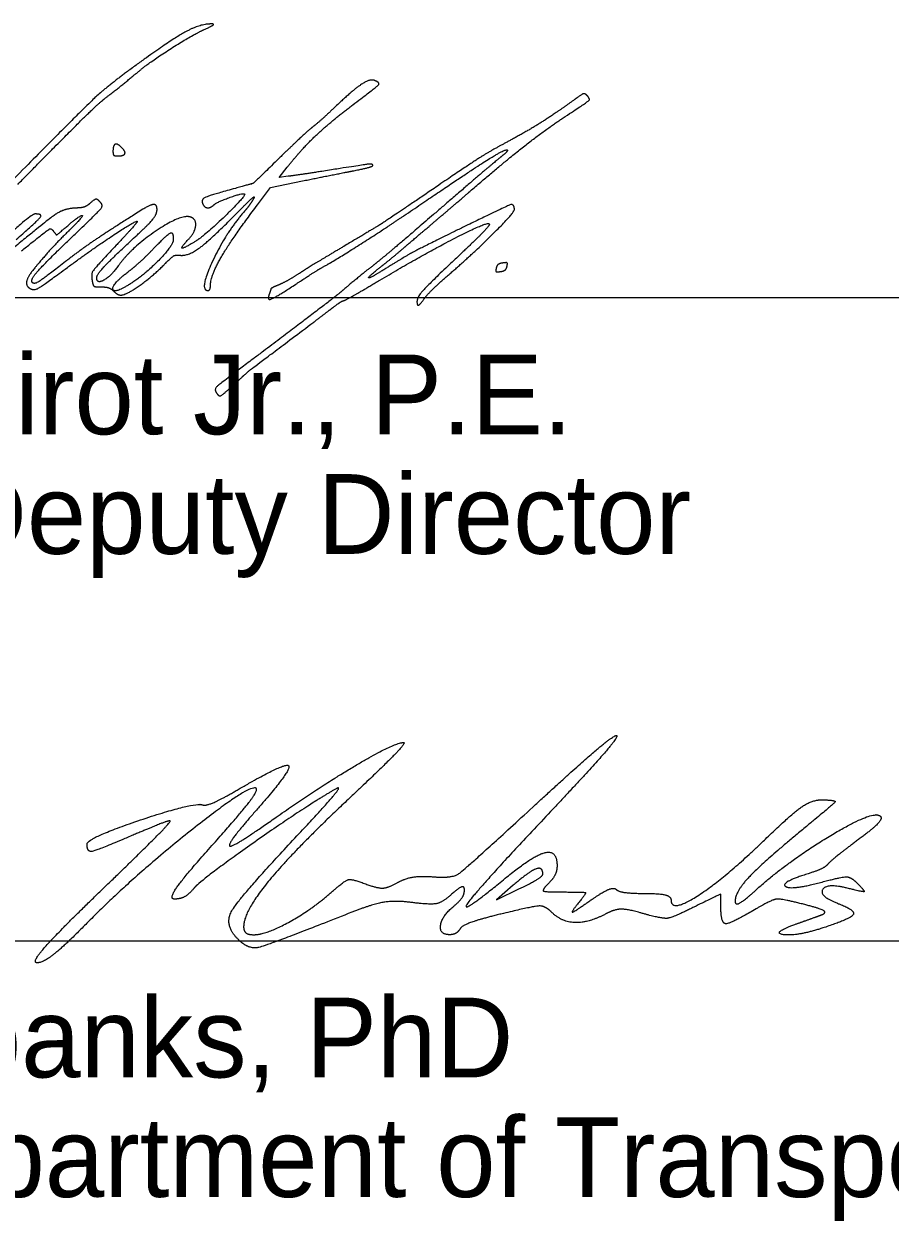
# Model space of a CAD drawing. Extents: x 0 to 34, y 0 to 22.
# Drawn here: x 25.594 to 27.114, y 7.177 to 9.279 of the extents above; entities that cross this region are included whole.
import ezdxf

# ---------------------------------------------------------------- set-up
doc = ezdxf.new("R2010")
doc.units = 0
doc.layers.add('SH_Data', color=7, linetype='Continuous')
doc.layers.add('SH_Text', color=7, linetype='Continuous')

msp = doc.modelspace()

# ---------------------------------------------------------------- linework, layer by layer
at = {"layer": 'SH_Data'}
for p, q in [((24.5279, 8.7985), (28.0279, 8.7985)), ((24.5279, 7.6691), (28.0279, 7.6691))]:
    msp.add_line(p, q, dxfattribs=at)
at = {"layer": 'SH_Text'}
for p, q in [((26.5045, 7.7863), (26.5045, 7.7863)), ((25.7273, 7.7552), (25.7273, 7.7552))]:
    msp.add_line(p, q, dxfattribs=at)
for points in [[(26.0579, 9.0115), (26.0419, 9.0095), (26.0559, 9.0273)], [(26.0039, 8.9616), (26.0269, 8.992), (26.083, 9.0034)], [(26.4527, 7.7666), (26.4232, 7.741), (26.4638, 7.7606)]]:
    msp.add_lwpolyline(points, dxfattribs=at)
for points in [[(25.9248, 9.279), (25.9035, 9.2798), (25.8469, 9.2481), (25.7754, 9.1954)], [(25.9102, 9.2692), (25.9219, 9.2745), (25.9284, 9.2789), (25.9248, 9.279)], [(25.7973, 9.1975), (25.8146, 9.2121), (25.8898, 9.2599), (25.9102, 9.2692)], [(25.7754, 9.1954), (25.7371, 9.1671), (25.6966, 9.1288), (25.567, 8.9978)], [(25.7351, 9.1475), (25.7574, 9.1649), (25.7844, 9.1866), (25.7973, 9.1975)], [(26.2088, 9.1799), (26.2008, 9.1829), (26.1702, 9.1621), (26.139, 9.1324)], [(26.1713, 9.137), (26.2132, 9.1687), (26.2194, 9.1758), (26.2088, 9.1799)], [(25.583, 8.9972), (25.6555, 9.0713), (25.724, 9.1389), (25.7351, 9.1475)], [(26.5615, 9.1472), (26.532, 9.1255), (26.4808, 9.0927), (26.4529, 9.0777)], [(26.5402, 9.1141), (26.5831, 9.1423), (26.5882, 9.1473), (26.5813, 9.1541)], [(26.5813, 9.1541), (26.5781, 9.1573), (26.5726, 9.1554), (26.5615, 9.1472)], [(26.0559, 9.0273), (26.0807, 9.0588), (26.1299, 9.1056), (26.1713, 9.137)], [(26.139, 9.1324), (26.1256, 9.1195), (26.1082, 9.104), (26.1004, 9.0978)], [(26.3772, 8.9855), (26.4315, 9.0325), (26.5078, 9.0927), (26.5402, 9.1141)], [(26.1004, 9.0978), (26.0925, 9.0916), (26.066, 9.0668), (26.0413, 9.0428)], [(25.7653, 9.0623), (25.7579, 9.0697), (25.7502, 9.066), (25.7502, 9.0551)], [(25.7581, 9.0472), (25.7691, 9.0472), (25.7728, 9.0549), (25.7653, 9.0623)], [(26.4529, 9.0777), (26.4131, 9.0563), (26.383, 9.0375), (26.3223, 8.9962)], [(25.7502, 9.0551), (25.7502, 9.05), (25.753, 9.0472), (25.7581, 9.0472)], [(26.0413, 9.0428), (25.9974, 8.9999), (25.9959, 8.9989), (25.965, 8.9903)], [(26.2612, 8.9425), (26.3674, 9.015), (26.4424, 9.0624), (26.4424, 9.0571)], [(26.4312, 9.0457), (26.4251, 9.0409), (26.3861, 9.0077), (26.3446, 8.9719)], [(26.4424, 9.0571), (26.4424, 9.0557), (26.4374, 9.0505), (26.4312, 9.0457)], [(26.1166, 9.0202), (26.0931, 9.0165), (26.0667, 9.0126), (26.0579, 9.0115)], [(26.083, 9.0034), (26.1138, 9.0097), (26.1542, 9.0177), (26.1726, 9.0213)], [(26.2062, 9.0307), (26.2062, 9.0337), (26.1895, 9.0317), (26.1166, 9.0202)], [(26.1726, 9.0213), (26.1911, 9.0249), (26.2062, 9.0292), (26.2062, 9.0307)], [(25.9811, 8.9805), (25.984, 8.9777), (25.9133, 8.909), (25.8969, 8.8986)], [(25.965, 8.9903), (25.9191, 8.9777), (25.9047, 8.971), (25.9075, 8.9637)], [(25.9276, 8.9616), (25.9324, 8.9663), (25.9789, 8.9828), (25.9811, 8.9805)], [(26.3223, 8.9962), (26.2337, 8.936), (26.2145, 8.9237), (26.1553, 8.8885)], [(26.3243, 8.9402), (26.3478, 8.9602), (26.3716, 8.9806), (26.3772, 8.9855)], [(25.6859, 8.9558), (25.6653, 8.9553), (25.6339, 8.9343), (25.5531, 8.867)], [(25.6818, 8.9082), (25.7239, 8.9487), (25.7332, 8.9596), (25.7295, 8.9642)], [(25.7087, 8.963), (25.7045, 8.9592), (25.6943, 8.9559), (25.6859, 8.9558)], [(25.7295, 8.9642), (25.7233, 8.9716), (25.7179, 8.9713), (25.7087, 8.963)], [(25.8275, 8.9527), (25.8276, 8.9619), (25.8169, 8.9623), (25.8027, 8.9535)], [(25.9075, 8.9637), (25.9102, 8.9568), (25.9216, 8.9556), (25.9276, 8.9616)], [(25.9212, 8.8193), (25.9212, 8.8369), (25.9595, 8.9028), (26.0039, 8.9616)], [(25.9678, 8.947), (25.9878, 8.9674), (26.0008, 8.9786), (25.9967, 8.9719)], [(25.9967, 8.9719), (25.9927, 8.9651), (25.9861, 8.956), (25.9822, 8.9515)], [(26.3446, 8.9719), (26.2759, 8.9125), (26.2222, 8.867), (26.2062, 8.8545)], [(26.4546, 8.9531), (26.4546, 8.9639), (26.4407, 8.9591), (26.3661, 8.9227)], [(25.6135, 8.9454), (25.6063, 8.9454), (25.4979, 8.844), (25.4978, 8.8373)], [(25.5805, 8.9005), (25.6185, 8.9337), (25.6271, 8.9454), (25.6135, 8.9454)], [(25.665, 8.9199), (25.6913, 8.9427), (25.7002, 8.9428), (25.6769, 8.92)], [(25.8027, 8.9535), (25.7468, 8.9186), (25.6936, 8.8827), (25.667, 8.8619)], [(25.8869, 8.9397), (25.8709, 8.9459), (25.7822, 8.8863), (25.7595, 8.8542)], [(25.789, 8.905), (25.8124, 8.9265), (25.8274, 8.9452), (25.8275, 8.9527)], [(25.8678, 8.8728), (25.8826, 8.8713), (25.9225, 8.9009), (25.9678, 8.947)], [(25.8818, 8.8998), (25.8939, 8.9125), (25.8969, 8.9359), (25.8869, 8.9397)], [(25.9822, 8.9515), (25.9489, 8.9136), (25.901, 8.811), (25.9166, 8.811)], [(26.1146, 8.8499), (26.1373, 8.8625), (26.2253, 8.9181), (26.2612, 8.9425)], [(26.2595, 8.8849), (26.2716, 8.8953), (26.3008, 8.9202), (26.3243, 8.9402)], [(26.3385, 8.8379), (26.3792, 8.8728), (26.4546, 8.9477), (26.4546, 8.9531)], [(25.5896, 8.8805), (25.6356, 8.9173), (25.6415, 8.9209), (25.646, 8.9147)], [(25.6769, 8.92), (25.6555, 8.899), (25.6324, 8.874), (25.6129, 8.8506)], [(25.646, 8.9147), (25.6507, 8.9083), (25.6523, 8.9088), (25.665, 8.9199)], [(25.6702, 8.8514), (25.714, 8.8837), (25.7909, 8.9346), (25.7929, 8.9326)], [(25.7929, 8.9326), (25.7936, 8.9318), (25.777, 8.9128), (25.7559, 8.8904)], [(26.2184, 8.8291), (26.3001, 8.8777), (26.4157, 8.9361), (26.4102, 8.9258)], [(26.3661, 8.9227), (26.2919, 8.8864), (26.2627, 8.8707), (26.2211, 8.8447)], [(26.4102, 8.9258), (26.4079, 8.9215), (26.3821, 8.8955), (26.3529, 8.868)], [(25.609, 8.8247), (25.6045, 8.8292), (25.6294, 8.8578), (25.6818, 8.9082)], [(25.7217, 8.8333), (25.7217, 8.8389), (25.7502, 8.8692), (25.789, 8.905)], [(25.8561, 8.9004), (25.8561, 8.8909), (25.8096, 8.8419), (25.7853, 8.8257)], [(25.821, 8.8841), (25.846, 8.9098), (25.8561, 8.9145), (25.8561, 8.9004)], [(25.8969, 8.8986), (25.8754, 8.8851), (25.8682, 8.8856), (25.8818, 8.8998)], [(25.7559, 8.8904), (25.7183, 8.8505), (25.7114, 8.8396), (25.7143, 8.8246)], [(25.7777, 8.8446), (25.7883, 8.8527), (25.8078, 8.8705), (25.821, 8.8841)], [(25.8393, 8.8557), (25.8528, 8.8695), (25.8597, 8.8737), (25.8678, 8.8728)], [(26.1553, 8.8885), (26.124, 8.8699), (26.0887, 8.8484), (26.077, 8.8408)], [(26.2197, 8.8522), (26.2295, 8.8598), (26.2474, 8.8745), (26.2595, 8.8849)], [(25.6129, 8.8506), (25.6011, 8.8364), (25.5968, 8.8194), (25.6039, 8.815)], [(25.6039, 8.815), (25.6111, 8.8105), (25.6255, 8.8184), (25.6702, 8.8514)], [(25.667, 8.8619), (25.6291, 8.8323), (25.6122, 8.8215), (25.609, 8.8247)], [(25.7595, 8.8542), (25.7466, 8.8359), (25.7217, 8.8222), (25.7217, 8.8333)], [(25.764, 8.8029), (25.773, 8.8029), (25.8198, 8.8357), (25.8393, 8.8557)], [(26.2062, 8.8545), (26.1938, 8.8449), (26.1553, 8.8131), (26.1533, 8.8109)], [(26.2211, 8.8447), (26.1993, 8.831), (26.1984, 8.8356), (26.2197, 8.8522)], [(26.3529, 8.868), (26.3016, 8.8197), (26.2813, 8.7955), (26.2844, 8.7863)], [(26.4227, 8.8504), (26.4216, 8.8446), (26.4234, 8.8433), (26.4308, 8.8443)], [(26.4336, 8.8592), (26.4283, 8.8585), (26.4235, 8.8545), (26.4227, 8.8504)], [(26.4308, 8.8443), (26.436, 8.845), (26.4409, 8.849), (26.4417, 8.8531)], [(26.4417, 8.8531), (26.4428, 8.8589), (26.4409, 8.8603), (26.4336, 8.8592)], [(25.7853, 8.8257), (25.7535, 8.8045), (25.7469, 8.8209), (25.7777, 8.8446)], [(26.077, 8.8408), (26.0653, 8.8332), (26.0492, 8.8243), (26.0414, 8.821)], [(26.0711, 8.8221), (26.0905, 8.8349), (26.1101, 8.8475), (26.1146, 8.8499)], [(26.2959, 8.7958), (26.3014, 8.8035), (26.3206, 8.8224), (26.3385, 8.8379)], [(25.7143, 8.8246), (25.7154, 8.8191), (25.7195, 8.8172), (25.7299, 8.8172)], [(25.7299, 8.8172), (25.738, 8.8173), (25.747, 8.8143), (25.7511, 8.8101)], [(25.7511, 8.8101), (25.7551, 8.8061), (25.7609, 8.8029), (25.764, 8.8029)], [(25.9166, 8.811), (25.9191, 8.811), (25.9212, 8.8148), (25.9212, 8.8193)], [(26.1533, 8.8109), (26.151, 8.8084), (26.0688, 8.7455), (25.9986, 8.6927)], [(26.0246, 8.8053), (26.0199, 8.793), (26.0353, 8.7986), (26.0711, 8.8221)], [(26.0271, 8.8134), (26.0271, 8.8124), (26.026, 8.8088), (26.0246, 8.8053)], [(26.0414, 8.821), (26.0335, 8.8177), (26.0271, 8.8143), (26.0271, 8.8134)], [(26.1552, 8.7932), (26.1575, 8.7936), (26.186, 8.8097), (26.2184, 8.8291)], [(26.1369, 8.7816), (26.1447, 8.7876), (26.153, 8.7928), (26.1552, 8.7932)], [(26.2844, 8.7863), (26.2852, 8.7838), (26.2904, 8.7881), (26.2959, 8.7958)], [(26.1024, 8.7554), (26.1136, 8.7638), (26.1291, 8.7756), (26.1369, 8.7816)], [(25.9616, 8.6451), (25.9862, 8.6678), (25.9937, 8.6737), (26.1024, 8.7554)], [(25.9986, 8.6927), (25.9381, 8.6471), (25.9277, 8.6378), (25.9311, 8.6323)], [(25.9311, 8.6323), (25.9359, 8.6246), (25.9421, 8.6272), (25.9616, 8.6451)], [(26.0326, 7.8833), (26.1131, 7.9399), (26.2445, 8.0172), (26.2602, 8.0172)], [(26.2602, 8.0172), (26.265, 8.0172), (26.2237, 7.9746), (26.1684, 7.9225)], [(26.4869, 7.9037), (26.5619, 7.9728), (26.6279, 8.0295), (26.6336, 8.0295)], [(26.6336, 8.0295), (26.6394, 8.0296), (26.5873, 7.9695), (26.518, 7.8959)], [(25.9736, 7.9368), (26.0524, 7.983), (26.0646, 7.9698), (26.0054, 7.9025)], [(26.0017, 7.9366), (25.9921, 7.9462), (25.7824, 7.7793), (25.7045, 7.7)], [(26.142, 7.9361), (26.0929, 7.9084), (25.9046, 7.7761), (25.8914, 7.7602)], [(25.908, 7.9076), (25.9136, 7.9058), (25.9431, 7.9189), (25.9736, 7.9368)], [(25.9239, 7.8362), (25.9702, 7.888), (26.0052, 7.9331), (26.0017, 7.9366)], [(26.0768, 7.8572), (26.123, 7.9065), (26.1523, 7.942), (26.142, 7.9361)], [(25.7047, 7.8391), (25.7049, 7.8496), (25.8923, 7.9128), (25.908, 7.9076)], [(26.1684, 7.9225), (26.0687, 7.8288), (25.9795, 7.7206), (25.9795, 7.6936)], [(26.8951, 7.8475), (26.9403, 7.8913), (26.9774, 7.917), (26.9951, 7.9166)], [(26.9951, 7.9166), (27.0194, 7.9161), (27.0156, 7.9098), (26.967, 7.8698)], [(26.0054, 7.9025), (25.9774, 7.8706), (25.9545, 7.841), (25.9545, 7.8365)], [(25.9545, 7.8365), (25.9545, 7.8321), (25.9896, 7.8531), (26.0326, 7.8833)], [(26.3119, 7.7814), (26.3453, 7.7786), (26.3688, 7.795), (26.4869, 7.9037)], [(26.518, 7.8959), (26.3885, 7.7583), (26.3564, 7.711), (26.4386, 7.7788)], [(26.8763, 7.7563), (26.93, 7.8051), (27.0769, 7.8951), (27.0938, 7.8895)], [(27.0938, 7.8895), (27.1022, 7.8867), (27.087, 7.868), (27.0599, 7.8478)], [(25.7273, 7.7552), (25.7983, 7.8237), (25.8537, 7.8797), (25.8502, 7.8797)], [(25.8502, 7.8797), (25.8468, 7.8797), (25.8178, 7.8684), (25.7857, 7.8547)], [(26.967, 7.8698), (26.8929, 7.8088), (26.842, 7.7553), (26.842, 7.7385)], [(25.7857, 7.8547), (25.7231, 7.8279), (25.7044, 7.8242), (25.7047, 7.8391)], [(25.9697, 7.6716), (25.9445, 7.6968), (25.9734, 7.7469), (26.0768, 7.8572)], [(26.7295, 7.7407), (26.7295, 7.7179), (26.8248, 7.7793), (26.8951, 7.8475)], [(27.0599, 7.8478), (27.0328, 7.8276), (27.0079, 7.8076), (27.0045, 7.8033)], [(25.8581, 7.7422), (25.8478, 7.7422), (25.8767, 7.7835), (25.9239, 7.8362)], [(26.4386, 7.7788), (26.487, 7.8187), (26.5295, 7.829), (26.5295, 7.8009)], [(26.5295, 7.8009), (26.5295, 7.792), (26.5227, 7.7779), (26.5145, 7.7697)], [(27.0045, 7.8033), (27.001, 7.7991), (26.9856, 7.7916), (26.9701, 7.7868)], [(26.2489, 7.7709), (26.2623, 7.7785), (26.2906, 7.7832), (26.3119, 7.7814)], [(26.5045, 7.7863), (26.5045, 7.7997), (26.4804, 7.7906), (26.4527, 7.7666)], [(26.4638, 7.7606), (26.4862, 7.7715), (26.5045, 7.783), (26.5045, 7.7863)], [(26.9701, 7.7868), (26.9206, 7.7713), (26.9401, 7.7577), (26.9919, 7.7715)], [(26.9919, 7.7715), (27.0302, 7.7817), (27.0455, 7.7811), (27.0575, 7.7689)], [(25.8914, 7.7602), (25.8831, 7.7503), (25.8682, 7.7422), (25.8581, 7.7422)], [(25.9975, 7.6797), (26.0192, 7.6797), (26.1006, 7.7249), (26.137, 7.7572)], [(26.137, 7.7572), (26.1573, 7.7752), (26.1701, 7.7779), (26.1939, 7.7688)], [(26.1939, 7.7688), (26.2141, 7.7612), (26.2329, 7.7619), (26.2489, 7.7709)], [(26.367, 7.7582), (26.367, 7.7653), (26.3568, 7.7619), (26.3444, 7.7506)], [(26.3482, 7.7297), (26.3585, 7.7382), (26.367, 7.7511), (26.367, 7.7582)], [(26.5145, 7.7697), (26.5028, 7.758), (26.5087, 7.7547), (26.541, 7.7547)], [(26.5871, 7.7392), (26.6085, 7.7542), (26.6293, 7.7632), (26.6332, 7.7593)], [(26.6332, 7.7593), (26.6371, 7.7554), (26.6604, 7.7522), (26.6849, 7.7522)], [(27.0388, 7.7614), (27.0021, 7.7705), (26.9889, 7.7474), (27.0232, 7.7342)], [(27.0575, 7.7689), (27.0702, 7.756), (27.0666, 7.7545), (27.0388, 7.7614)], [(25.617, 7.6304), (25.6067, 7.6306), (25.6563, 7.6868), (25.7273, 7.7552)], [(26.2749, 7.7362), (26.2457, 7.74), (26.2058, 7.7335), (26.1693, 7.7191)], [(26.3444, 7.7506), (26.3287, 7.7365), (26.3075, 7.732), (26.2749, 7.7362)], [(26.541, 7.7547), (26.5785, 7.7547), (26.5809, 7.7526), (26.5654, 7.7333)], [(26.5654, 7.7333), (26.5533, 7.7183), (26.5598, 7.7201), (26.5871, 7.7392)], [(26.6849, 7.7522), (26.7094, 7.7522), (26.7295, 7.747), (26.7295, 7.7407)], [(26.817, 7.7281), (26.817, 7.751), (26.8159, 7.751), (26.7698, 7.7282)], [(26.842, 7.7385), (26.842, 7.7311), (26.8574, 7.7391), (26.8763, 7.7563)], [(26.9621, 7.7331), (26.9233, 7.743), (26.9065, 7.7414), (26.8789, 7.7251)], [(26.1693, 7.7191), (26.0233, 7.6614), (25.9882, 7.6531), (25.9697, 7.6716)], [(26.3412, 7.6797), (26.3229, 7.6797), (26.3274, 7.7124), (26.3482, 7.7297)], [(26.4355, 7.7171), (26.3972, 7.7079), (26.3629, 7.6958), (26.3594, 7.6901)], [(26.5199, 7.7193), (26.5088, 7.7304), (26.4887, 7.7299), (26.4355, 7.7171)], [(26.6162, 7.7168), (26.5854, 7.7003), (26.5376, 7.7016), (26.5199, 7.7193)], [(26.6807, 7.7168), (26.6538, 7.7246), (26.6307, 7.7245), (26.6162, 7.7168)], [(26.7698, 7.7282), (26.7324, 7.7097), (26.7138, 7.7073), (26.6807, 7.7168)], [(26.8789, 7.7251), (26.8339, 7.6985), (26.817, 7.6993), (26.817, 7.7281)], [(26.992, 7.7139), (27.0034, 7.7181), (26.9917, 7.7256), (26.9621, 7.7331)], [(27.0232, 7.7342), (27.0538, 7.7225), (27.0449, 7.7076), (26.9981, 7.6922)], [(25.7045, 7.7), (25.6667, 7.6615), (25.6273, 7.6302), (25.617, 7.6304)], [(26.9981, 7.6922), (26.9515, 7.6768), (26.9042, 7.6825), (26.9482, 7.6982)], [(26.9482, 7.6982), (26.962, 7.7031), (26.9817, 7.7102), (26.992, 7.7139)], [(25.9795, 7.6936), (25.9795, 7.686), (25.9876, 7.6797), (25.9975, 7.6797)], [(26.3594, 7.6901), (26.3559, 7.6844), (26.3477, 7.6797), (26.3412, 7.6797)]]:
    msp.add_open_spline(points, degree=2, dxfattribs=at)

# ---------------------------------------------------------------- texts
for s, p in [('Arthur G. Noirot Jr., P.E.', (24.5279, 8.5585)), ('District       Deputy Director', (24.5279, 8.3485)), ('Jack Marchbanks, PhD', (24.5279, 7.4291)), ('Director, Department of Transportation', (24.5279, 7.2191))]:
    msp.add_text(s, height=0.14, dxfattribs=at).set_placement(p)

doc.saveas('drawing.dxf')
